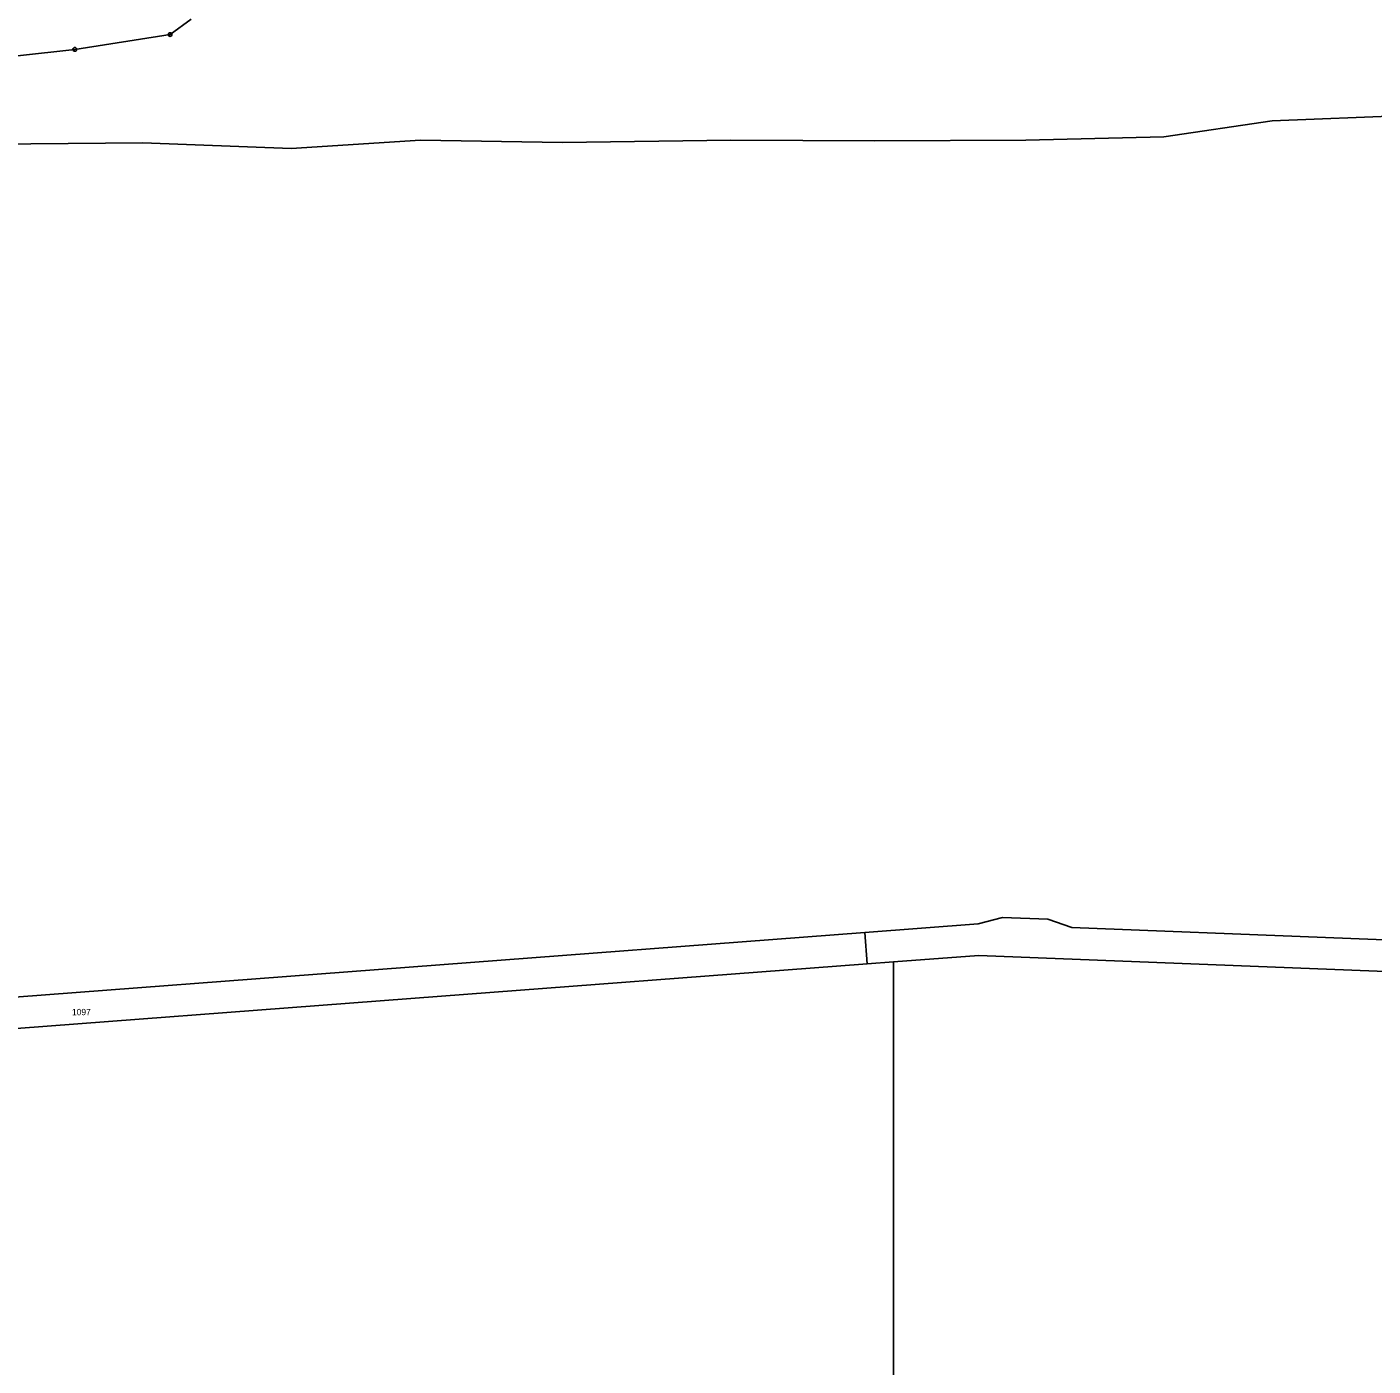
# Model space of a CAD drawing. Extents: x -758887 to -754328, y -1031688 to -1029144.
# Drawn here: x -757650.6 to -757288.4, y -1029967.8 to -1029607.4 of the extents above; entities that cross this region are included whole.
import ezdxf
from ezdxf.enums import TextEntityAlignment as Align

# ---------------------------------------------------------------- set-up
doc = ezdxf.new("R2010")
doc.units = 0
doc.header["$LTSCALE"] = 0.68
doc.layers.add('1', color=7, linetype='Continuous', lineweight=25)
doc.layers.add('8', color=7, linetype='Continuous', lineweight=25)
doc.layers.add('2', color=7, linetype='Continuous')

msp = doc.modelspace()

# ---------------------------------------------------------------- linework, layer by layer
at = {"layer": '1'}
for p in [(-757425.2, -1029851.06), (-757417.5, -1029859)]:
    msp.add_line(p, (-757424.56, -1029859.54), dxfattribs=at)
for points in [[(-757859.58, -1029641.76), (-757797.61, -1029632.64), (-757730.43, -1029623.69), (-757637.77, -1029613.41), (-757612.12, -1029609.42), (-757606.43, -1029605.31)], [(-757279.49, -1029631.19), (-757315.6, -1029632.63), (-757344.73, -1029636.99), (-757381.92, -1029637.83), (-757422.5, -1029638.06), (-757461.24, -1029637.87), (-757506.58, -1029638.5), (-757544.78, -1029637.83), (-757579.53, -1029640.11), (-757619.47, -1029638.52), (-757659.7, -1029638.94), (-757683.31, -1029641.04), (-757718.54, -1029643.48), (-757737.31, -1029641.54), (-757771.17, -1029644.98), (-757807.74, -1029649.7), (-757842.34, -1029655.09), (-757854.31, -1029657.32)], [(-757854.31, -1029657.32), (-757854.05, -1029658.08), (-757852.99, -1029659.62), (-757834.25, -1029680.11), (-757796.39, -1029722.57), (-757677.7, -1029866.65), (-757677.03, -1029867.41), (-757675.39, -1029868.64), (-757673.52, -1029869.44), (-757671.5, -1029869.77), (-757670.48, -1029869.72), (-757547.84, -1029860.39), (-757425.2, -1029851.06)], [(-757424.56, -1029859.54), (-757547.33, -1029868.88), (-757670.09, -1029878.21), (-757672, -1029878.3), (-757675.91, -1029877.66), (-757679.67, -1029876.06), (-757682.84, -1029873.68), (-757684.1, -1029872.24), (-757802.97, -1029727.92), (-757840.27, -1029686.1), (-757860.31, -1029664.36), (-757862.06, -1029660.91), (-757862.75, -1029659.15), (-757862.8, -1029658.9)], [(-757425.2, -1029851.06), (-757394.71, -1029848.74), (-757388.13, -1029847.09), (-757375.99, -1029847.54), (-757369.5, -1029849.74), (-757232.98, -1029855.14), (-757096.45, -1029860.53), (-757010.13, -1029867.2), (-757003.6, -1029865.78), (-756991.45, -1029866.71), (-756985.13, -1029869.15), (-756860.29, -1029878.8), (-756799.45, -1029887.43), (-756703.79, -1029907.22), (-756698.01, -1029907.91)], [(-757278.2, -1029861.84), (-757394.49, -1029857.25), (-757417.5, -1029859)], [(-757417.5, -1029859), (-757417.5, -1030024.75), (-757417.5, -1030190.49)]]:
    msp.add_lwpolyline(points, dxfattribs=at)
at = {"layer": '8'}
for centre, radius in [((-757612.12, -1029609.4199), 0.5), ((-757612.12, -1029609.4199), 0.0303), ((-757637.77, -1029613.4099), 0.5), ((-757637.77, -1029613.4099), 0.0303)]:
    msp.add_circle(centre, radius, dxfattribs=at)

# ---------------------------------------------------------------- texts
at = {"layer": '2'}
msp.add_text('1097', height=1.7, dxfattribs=at).set_placement((-757636, -1029873.356), align=Align.CENTER)

doc.saveas('drawing.dxf')
